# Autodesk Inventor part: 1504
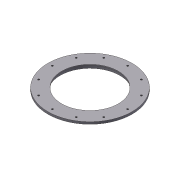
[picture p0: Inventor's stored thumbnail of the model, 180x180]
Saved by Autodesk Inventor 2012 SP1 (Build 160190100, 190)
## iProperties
Created: 2012-02
Part Number: 1504
Material: Aluminum-6061
Document SubType Name: Modeling
Designer: LACO
Density: 2.71 g/cm^3
Mass: 699.771 g
Surface Area: 705.041 cm^2
Volume: 258.218 cm^3
Author: LACO
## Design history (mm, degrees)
sketch "Sketch1"
  geometry: L1 (0, 0)-(-41.198, 0); L2 (0, 0)-(0, -19.072); L3 (-120.65, 0)-(-120.65, -6.35); L4 (-120.65, -6.35)-(-88.9, -6.35); L5 (-88.9, -6.35)-(-88.9, -12.7); L6 (-88.9, -12.7)-(-85.344, -12.7); L7 (-85.344, -12.7)-(-85.344, -3.175); L8 (-85.344, -3.175)-(-81.28, -3.175); L9 (-81.28, -3.175)-(-81.28, 0); L10 (-81.28, 0)-(-120.65, 0)
  constraints: 20 end point, 7 parallel, 2 perpendicular, 1 collinear, 1 horizontal
  dimensions: "d0" = 162.56 diameter of L9 L2; "d1" = 241.3 diameter of L3 L2; "d2" = 170.688 diameter of L7 L2; "d3" = 177.8 diameter of L5 L2; "d4" = 6.35 distance between parallel lines of L4 L10; "d5" = 6.35 distance between parallel lines of L6 L4; "d6" = 3.175 distance between parallel lines of L10 L8
revolve "Revolution1" sketch "Sketch1" stored, may be unused: angle "d7" = 90 deg
sketch "Sketch2"
  geometry: L1 (0, 0)-(107.95, 0); C1 r 88.9 at (0, 0) reference; 1 further point
  constraints: 2 end point, 1 coincident, 1 horizontal
  dimensions: "d8" = 107.95 distance of L1.start L1.end
hole "Hole1" sketch "Sketch2" at (107.95, 0) diameter "d9" = 4.9784; stored, may be unused: countersink angle "d13" = 82 deg, drill point angle "d15" = 118 deg; dims "d10" = 19.05, "d11" = 12.8778, "d12" = 6.35, "d14" = 25.4
pattern_circular "Circular Pattern1" dims angle "d17" = 360 deg
body "Solid1"
